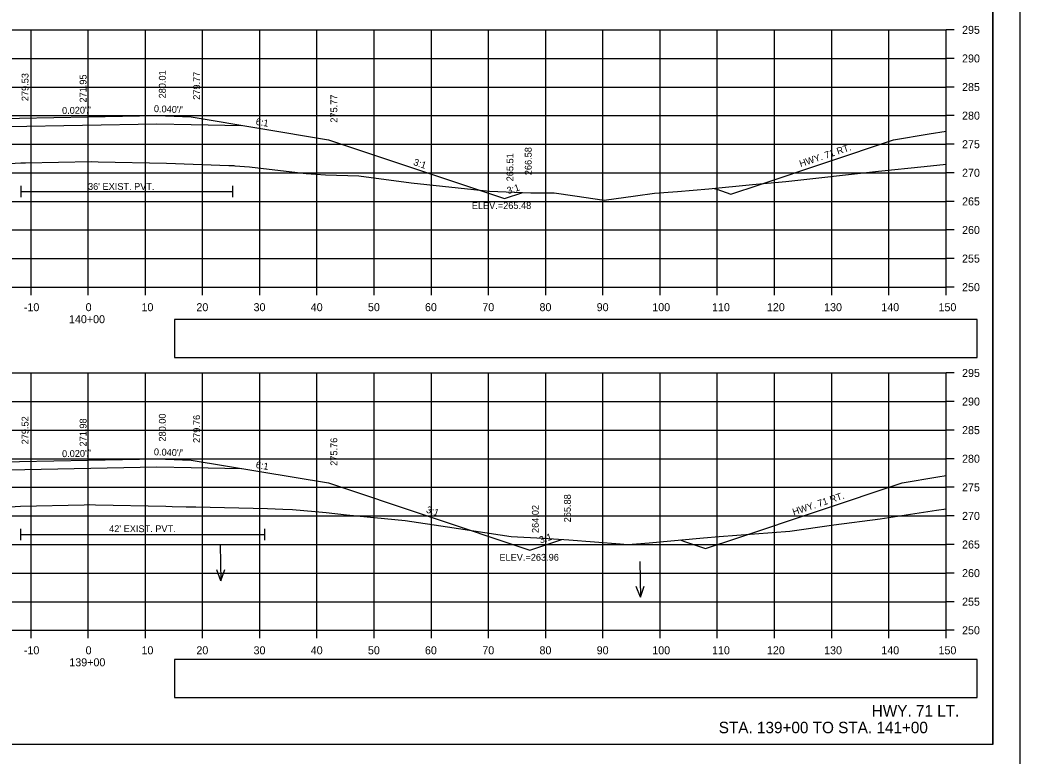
# Model space of a CAD drawing. Extents: x 285 to 4233, y -659 to 3710.
# Drawn here: x 527.3 to 702.2, y 2538.2 to 2666.9 of the extents above; entities that cross this region are included whole.
import ezdxf

# ---------------------------------------------------------------- set-up
doc = ezdxf.new("R2010")
doc.units = 0
for name, color, linetype in [('R_Alt Surface', 7, 'Continuous'), ('R_Axis', 7, 'Continuous'), ('R_Axis Annot', 7, 'Continuous'), ('R_Border', 7, 'Continuous'), ('R_Draft', 7, 'Continuous'), ('R_Exist Surface', 7, 'Continuous'), ('R_Fin Surface', 7, 'Continuous'), ('R_Grid', 7, 'Continuous'), ('R_No Plot', 7, 'Continuous'), ('R_Proposed Const Limits', 7, 'Continuous'), ('R_Water', 7, 'Continuous'), ('R_Water Annot', 7, 'Continuous'), ('R_Xsect Elev', 7, 'Continuous'), ('R_Xsect Slope', 7, 'Continuous')]:
    doc.layers.add(name, color=color, linetype=linetype)

msp = doc.modelspace()

# ---------------------------------------------------------------- linework, layer by layer
at = {"layer": 'R_Alt Surface'}
for points in [[(508.71, 2647.95), (517.28, 2648.12), (525.28, 2648.28), (551.28, 2648.8), (551.28, 2648.8), (557.28, 2648.68), (566.12, 2648.51)], [(527.52, 2637.93), (527.52, 2635.93)], [(564.48, 2637.93), (564.48, 2635.93)], [(527.52, 2636.93), (564.48, 2636.93)], [(508.71, 2587.94), (517.28, 2588.11), (525.28, 2588.27), (551.28, 2588.79), (551.28, 2588.79), (557.28, 2588.67), (566.12, 2588.49)], [(527.41, 2577.94), (527.41, 2575.94)], [(570.1, 2577.94), (570.1, 2575.94)], [(527.41, 2576.94), (570.1, 2576.94)]]:
    msp.add_lwpolyline(points, dxfattribs=at)
at = {"layer": 'R_Axis'}
for p, q in [((689.28, 2620.21), (689.28, 2665.21)), ((690.68, 2665.21), (689.28, 2665.21)), ((690.68, 2660.21), (689.28, 2660.21)), ((690.68, 2655.21), (689.28, 2655.21)), ((690.68, 2650.21), (689.28, 2650.21)), ((690.68, 2645.21), (689.28, 2645.21)), ((690.68, 2640.21), (689.28, 2640.21)), ((690.68, 2635.21), (689.28, 2635.21)), ((690.68, 2630.21), (689.28, 2630.21)), ((690.68, 2625.21), (689.28, 2625.21)), ((389.28, 2620.21), (689.28, 2620.21)), ((529.28, 2618.81), (529.28, 2620.21)), ((539.28, 2618.81), (539.28, 2620.21)), ((549.28, 2618.81), (549.28, 2620.21)), ((559.28, 2618.81), (559.28, 2620.21)), ((569.28, 2618.81), (569.28, 2620.21)), ((579.28, 2618.81), (579.28, 2620.21)), ((589.28, 2618.81), (589.28, 2620.21)), ((599.28, 2618.81), (599.28, 2620.21)), ((609.28, 2618.81), (609.28, 2620.21)), ((619.28, 2618.81), (619.28, 2620.21)), ((629.28, 2618.81), (629.28, 2620.21)), ((639.28, 2618.81), (639.28, 2620.21)), ((649.28, 2618.81), (649.28, 2620.21)), ((659.28, 2618.81), (659.28, 2620.21)), ((669.28, 2618.81), (669.28, 2620.21)), ((679.28, 2618.81), (679.28, 2620.21)), ((689.28, 2618.81), (689.28, 2620.21)), ((690.68, 2620.21), (689.28, 2620.21)), ((689.28, 2560.21), (689.28, 2605.21)), ((690.68, 2605.21), (689.28, 2605.21)), ((690.68, 2600.21), (689.28, 2600.21)), ((690.68, 2595.21), (689.28, 2595.21)), ((690.68, 2590.21), (689.28, 2590.21)), ((690.68, 2585.21), (689.28, 2585.21)), ((690.68, 2580.21), (689.28, 2580.21)), ((690.68, 2575.21), (689.28, 2575.21)), ((690.68, 2570.21), (689.28, 2570.21)), ((690.68, 2565.21), (689.28, 2565.21)), ((389.28, 2560.21), (689.28, 2560.21)), ((529.28, 2558.81), (529.28, 2560.21)), ((539.28, 2558.81), (539.28, 2560.21)), ((549.28, 2558.81), (549.28, 2560.21)), ((559.28, 2558.81), (559.28, 2560.21)), ((569.28, 2558.81), (569.28, 2560.21)), ((579.28, 2558.81), (579.28, 2560.21)), ((589.28, 2558.81), (589.28, 2560.21)), ((599.28, 2558.81), (599.28, 2560.21)), ((609.28, 2558.81), (609.28, 2560.21)), ((619.28, 2558.81), (619.28, 2560.21)), ((629.28, 2558.81), (629.28, 2560.21)), ((639.28, 2558.81), (639.28, 2560.21)), ((649.28, 2558.81), (649.28, 2560.21)), ((659.28, 2558.81), (659.28, 2560.21)), ((669.28, 2558.81), (669.28, 2560.21)), ((679.28, 2558.81), (679.28, 2560.21)), ((689.28, 2558.81), (689.28, 2560.21)), ((690.68, 2560.21), (689.28, 2560.21))]:
    msp.add_line(p, q, dxfattribs=at)
at = {"layer": 'R_Axis Annot'}
for points in [[(554.36, 2607.89), (694.72, 2607.89), (694.72, 2614.54), (554.36, 2614.54)], [(554.36, 2548.45), (694.72, 2548.45), (694.72, 2555.1), (554.36, 2555.1)]]:
    msp.add_lwpolyline(points, close=True, dxfattribs=at)
at = {"layer": 'R_Border'}
for q in [(697.46, 2745.67), (381.28, 2540.21)]:
    msp.add_line((697.46, 2540.21), q, dxfattribs=at)
at = {"layer": 'R_Exist Surface'}
for points in [[(518.6, 2641.43), (527.52, 2641.93), (528.3, 2641.95), (539.84, 2642.17), (541, 2642.14), (552.94, 2641.92), (563.84, 2641.5), (564.74, 2641.46), (564.93, 2641.45), (567.45, 2641.26), (568.93, 2641.08), (577.36, 2640.07), (580.78, 2639.88), (586.58, 2639.66), (595.74, 2638.46), (609.45, 2637.02), (616.7, 2636.73), (620.73, 2636.7), (624.34, 2636.17), (629.48, 2635.41), (634.99, 2636.16), (638.27, 2636.65), (642.31, 2636.95), (647.81, 2637.38), (655.45, 2638.15), (661.28, 2638.67), (677.48, 2640.48), (685.47, 2641.33), (689.28, 2641.71)], [(519.13, 2581.37), (527.41, 2581.94), (538.54, 2582.17), (539.53, 2582.19), (540.53, 2582.17), (552.83, 2581.92), (553.97, 2581.88), (556.42, 2581.81), (558.08, 2581.77), (570.65, 2581.51), (573.29, 2581.39), (574.97, 2581.31), (578.98, 2580.96), (580.86, 2580.78), (580.86, 2580.78), (584.46, 2580.42), (594.67, 2579.39), (602.13, 2578.32), (613.23, 2576.61), (618.83, 2576.29), (623.33, 2576.02), (632.27, 2575.31), (633.6, 2575.2), (634.39, 2575.26), (637.35, 2575.53), (646.87, 2576.38), (649.58, 2576.6), (661.99, 2577.57), (669.67, 2578.65), (677.76, 2579.7), (687.59, 2581.23), (689.28, 2581.47)]]:
    msp.add_lwpolyline(points, dxfattribs=at)
at = {"layer": 'R_Fin Surface'}
for points in [[(461.93, 2638.04), (467.6, 2636.15), (497.28, 2646.05), (517.28, 2649.38), (525.28, 2649.7), (527.28, 2649.74), (551.28, 2650.22), (557.28, 2649.98), (581.28, 2645.98), (612.07, 2635.72), (615.27, 2636.79)], [(648.73, 2637.48), (649.18, 2637.32), (651.67, 2636.49), (656.58, 2638.13), (680.1, 2645.97), (686.33, 2647.01), (689.28, 2647.5)], [(458.23, 2577.26), (464.59, 2575.14), (497.28, 2586.04), (517.28, 2589.37), (525.28, 2589.69), (527.28, 2589.73), (551.28, 2590.21), (557.28, 2589.97), (581.28, 2585.97), (616.51, 2574.22), (622.12, 2576.09)], [(642.77, 2576.02), (643.37, 2575.81), (647.24, 2574.52), (652.69, 2576.34), (681.58, 2585.97), (687.87, 2587.02), (689.28, 2587.25)]]:
    msp.add_lwpolyline(points, dxfattribs=at)
at = {"layer": 'R_Grid'}
for p, q in [((389.28, 2665.21), (689.28, 2665.21)), ((529.28, 2620.21), (529.28, 2665.21)), ((539.28, 2620.21), (539.28, 2665.21)), ((549.28, 2620.21), (549.28, 2665.21)), ((559.28, 2620.21), (559.28, 2665.21)), ((569.28, 2620.21), (569.28, 2665.21)), ((579.28, 2620.21), (579.28, 2665.21)), ((589.28, 2620.21), (589.28, 2665.21)), ((599.28, 2620.21), (599.28, 2665.21)), ((609.28, 2620.21), (609.28, 2665.21)), ((619.28, 2620.21), (619.28, 2665.21)), ((629.28, 2620.21), (629.28, 2665.21)), ((639.28, 2620.21), (639.28, 2665.21)), ((649.28, 2620.21), (649.28, 2665.21)), ((659.28, 2620.21), (659.28, 2665.21)), ((669.28, 2620.21), (669.28, 2665.21)), ((679.28, 2620.21), (679.28, 2665.21)), ((689.28, 2620.21), (689.28, 2665.21)), ((389.28, 2660.21), (689.28, 2660.21)), ((389.28, 2655.21), (689.28, 2655.21)), ((389.28, 2650.21), (689.28, 2650.21)), ((389.28, 2645.21), (689.28, 2645.21)), ((389.28, 2640.21), (689.28, 2640.21)), ((389.28, 2635.21), (689.28, 2635.21)), ((389.28, 2630.21), (689.28, 2630.21)), ((389.28, 2625.21), (689.28, 2625.21)), ((389.28, 2620.21), (689.28, 2620.21)), ((389.28, 2605.21), (689.28, 2605.21)), ((529.28, 2560.21), (529.28, 2605.21)), ((539.28, 2560.21), (539.28, 2605.21)), ((549.28, 2560.21), (549.28, 2605.21)), ((559.28, 2560.21), (559.28, 2605.21)), ((569.28, 2560.21), (569.28, 2605.21)), ((579.28, 2560.21), (579.28, 2605.21)), ((589.28, 2560.21), (589.28, 2605.21)), ((599.28, 2560.21), (599.28, 2605.21)), ((609.28, 2560.21), (609.28, 2605.21)), ((619.28, 2560.21), (619.28, 2605.21)), ((629.28, 2560.21), (629.28, 2605.21)), ((639.28, 2560.21), (639.28, 2605.21)), ((649.28, 2560.21), (649.28, 2605.21)), ((659.28, 2560.21), (659.28, 2605.21)), ((669.28, 2560.21), (669.28, 2605.21)), ((679.28, 2560.21), (679.28, 2605.21)), ((689.28, 2560.21), (689.28, 2605.21)), ((389.28, 2600.21), (689.28, 2600.21)), ((389.28, 2595.21), (689.28, 2595.21)), ((389.28, 2590.21), (689.28, 2590.21)), ((389.28, 2585.21), (689.28, 2585.21)), ((389.28, 2580.21), (689.28, 2580.21)), ((389.28, 2575.21), (689.28, 2575.21)), ((389.28, 2570.21), (689.28, 2570.21)), ((389.28, 2565.21), (689.28, 2565.21)), ((389.28, 2560.21), (689.28, 2560.21))]:
    msp.add_line(p, q, dxfattribs=at)
at = {"layer": 'R_No Plot'}
for points in [[(368.87, 2749.56), (702.21, 2749.56), (702.21, 2536.23), (368.87, 2536.23)], [(615.2, 2745.67), (634.82, 2745.67), (634.82, 2735.79), (650.93, 2735.79), (674.13, 2735.79), (674.25, 2707.63), (697.46, 2707.63), (697.46, 2540.21), (381.28, 2540.21), (381.28, 2745.67)]]:
    msp.add_lwpolyline(points, close=True, dxfattribs=at)
at = {"layer": 'R_Proposed Const Limits'}
for points in [[(551.28, 2650.21), (551.28, 2650.22), (551.28, 2650.22), (551.28, 2650.23), (551.28, 2650.23), (551.28, 2650.24)], [(551.28, 2590.21), (551.28, 2590.21), (551.28, 2590.21)]]:
    msp.add_lwpolyline(points, dxfattribs=at)
at = {"layer": 'R_Water Annot'}
for p, q in [((562.36, 2575.17), (562.47, 2568.88)), ((562.47, 2568.88), (561.74, 2570.8)), ((562.47, 2568.88), (563.14, 2570.82)), ((635.72, 2572.26), (635.83, 2565.98)), ((635.83, 2565.98), (635.09, 2567.89)), ((635.83, 2565.98), (636.49, 2567.92))]:
    msp.add_line(p, q, dxfattribs=at)
at = {"layer": 'R_Xsect Elev'}
for p, q in [((539.28, 2642.16), (539.28, 2657.69)), ((539.28, 2582.19), (539.28, 2597.41))]:
    msp.add_line(p, q, dxfattribs=at)

# ---------------------------------------------------------------- texts
at = {"layer": 'R_Axis Annot'}
for s, p in [('295', (692.08, 2664.51)), ('290', (692.08, 2659.51)), ('285', (692.08, 2654.51)), ('280', (692.08, 2649.51)), ('275', (692.08, 2644.51)), ('270', (692.08, 2639.51)), ('265', (692.08, 2634.51)), ('260', (692.08, 2629.51)), ('255', (692.08, 2624.51)), ('250', (692.08, 2619.51)), ('-10', (528.02, 2616.01)), ('0', (538.82, 2616.01)), ('10', (548.59, 2616.01)), ('20', (558.19, 2616.01)), ('30', (568.19, 2616.01)), ('40', (578.19, 2616.01)), ('50', (588.19, 2616.01)), ('60', (598.16, 2616.01)), ('70', (608.19, 2616.01)), ('80', (618.19, 2616.01)), ('90', (628.19, 2616.01)), ('100', (637.91, 2616.01)), ('110', (648.36, 2616.01)), ('120', (657.96, 2616.01)), ('130', (667.96, 2616.01)), ('140', (677.96, 2616.01)), ('150', (687.96, 2616.01)), ('140+00', (535.91, 2613.91)), ('295', (692.08, 2604.51)), ('290', (692.08, 2599.51)), ('285', (692.08, 2594.51)), ('280', (692.08, 2589.51)), ('275', (692.08, 2584.51)), ('270', (692.08, 2579.51)), ('265', (692.08, 2574.51)), ('260', (692.08, 2569.51)), ('255', (692.08, 2564.51)), ('250', (692.08, 2559.51)), ('-10', (528.02, 2556.01)), ('0', (538.82, 2556.01)), ('10', (548.59, 2556.01)), ('20', (558.19, 2556.01)), ('30', (568.19, 2556.01)), ('40', (578.19, 2556.01)), ('50', (588.19, 2556.01)), ('60', (598.16, 2556.01)), ('70', (608.19, 2556.01)), ('80', (618.19, 2556.01)), ('90', (628.19, 2556.01)), ('100', (637.91, 2556.01)), ('110', (648.36, 2556.01)), ('120', (657.96, 2556.01)), ('130', (667.96, 2556.01)), ('140', (677.96, 2556.01)), ('150', (687.96, 2556.01)), ('139+00', (535.97, 2553.91))]:
    msp.add_text(s, height=1.4, dxfattribs=at).set_placement(p)
at = {"layer": 'R_Draft'}
for s, p in [('HWY. 71 LT.', (676.29, 2545.12)), ('STA. 139+00 TO STA. 141+00', (649.53, 2542.21))]:
    msp.add_text(s, height=2, dxfattribs=at).set_placement(p)
at = {"layer": 'R_Water'}
for p in [(663.86, 2641.19), (662.65, 2580.29)]:
    msp.add_text('HWY. 71 RT.', height=1.2, rotation=18.4331, dxfattribs=at).set_placement(p)
for s, p in [("36' EXIST. PVT.", (539.24, 2637.22)), ("42' EXIST. PVT.", (542.93, 2577.37))]:
    msp.add_text(s, height=1.2, dxfattribs=at).set_placement(p)
at = {"layer": 'R_Xsect Elev'}
for s, p in [('280.01', (552.83, 2653.22)), ('279.53', (528.83, 2652.74)), ('271.95', (538.98, 2652.5)), ('279.77', (558.83, 2652.98)), ('275.77', (582.83, 2648.98)), ('266.58', (616.82, 2639.79)), ('265.51', (613.62, 2638.72)), ('279.52', (528.83, 2592.73)), ('271.98', (538.98, 2592.35)), ('280.00', (552.83, 2593.21)), ('279.76', (558.83, 2592.97)), ('275.76', (582.83, 2588.97)), ('265.88', (623.67, 2579.09)), ('264.02', (618.06, 2577.22))]:
    msp.add_text(s, height=1.2, rotation=90, dxfattribs=at).set_placement(p)
for s, p in [('ELEV.=265.48', (606.35, 2633.89)), ('ELEV.=263.96', (611.18, 2572.37))]:
    msp.add_text(s, height=1.2, dxfattribs=at).set_placement(p)
at = {"layer": 'R_Xsect Slope'}
for s, rotation, p in [("0.020'/'", 1.1458, (534.71, 2650.49)), ("0.040'/'", 357.7094, (550.74, 2650.84)), ('6:1', 350.5377, (568.51, 2648.62)), ('3:1', 341.5651, (596.04, 2641.59)), ('3:1', 18.4349, (612.72, 2636.46)), ("0.020'/'", 1.1458, (534.71, 2590.48)), ("0.040'/'", 357.7094, (550.74, 2590.83)), ('6:1', 350.5377, (568.51, 2588.6)), ('3:1', 341.5651, (598.27, 2580.83)), ('3:1', 18.4349, (618.37, 2575.37))]:
    msp.add_text(s, height=1.2, rotation=rotation, dxfattribs=at).set_placement(p)

doc.saveas('drawing.dxf')
